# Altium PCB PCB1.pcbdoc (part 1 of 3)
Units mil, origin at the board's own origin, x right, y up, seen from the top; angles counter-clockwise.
Board outline 5971.11 x 4241.46 mil, 4 copper layers (Top Layer, Inner1, Inner2, Bottom Layer); 197 components, 112 nets, 603 pads, 396 vias.
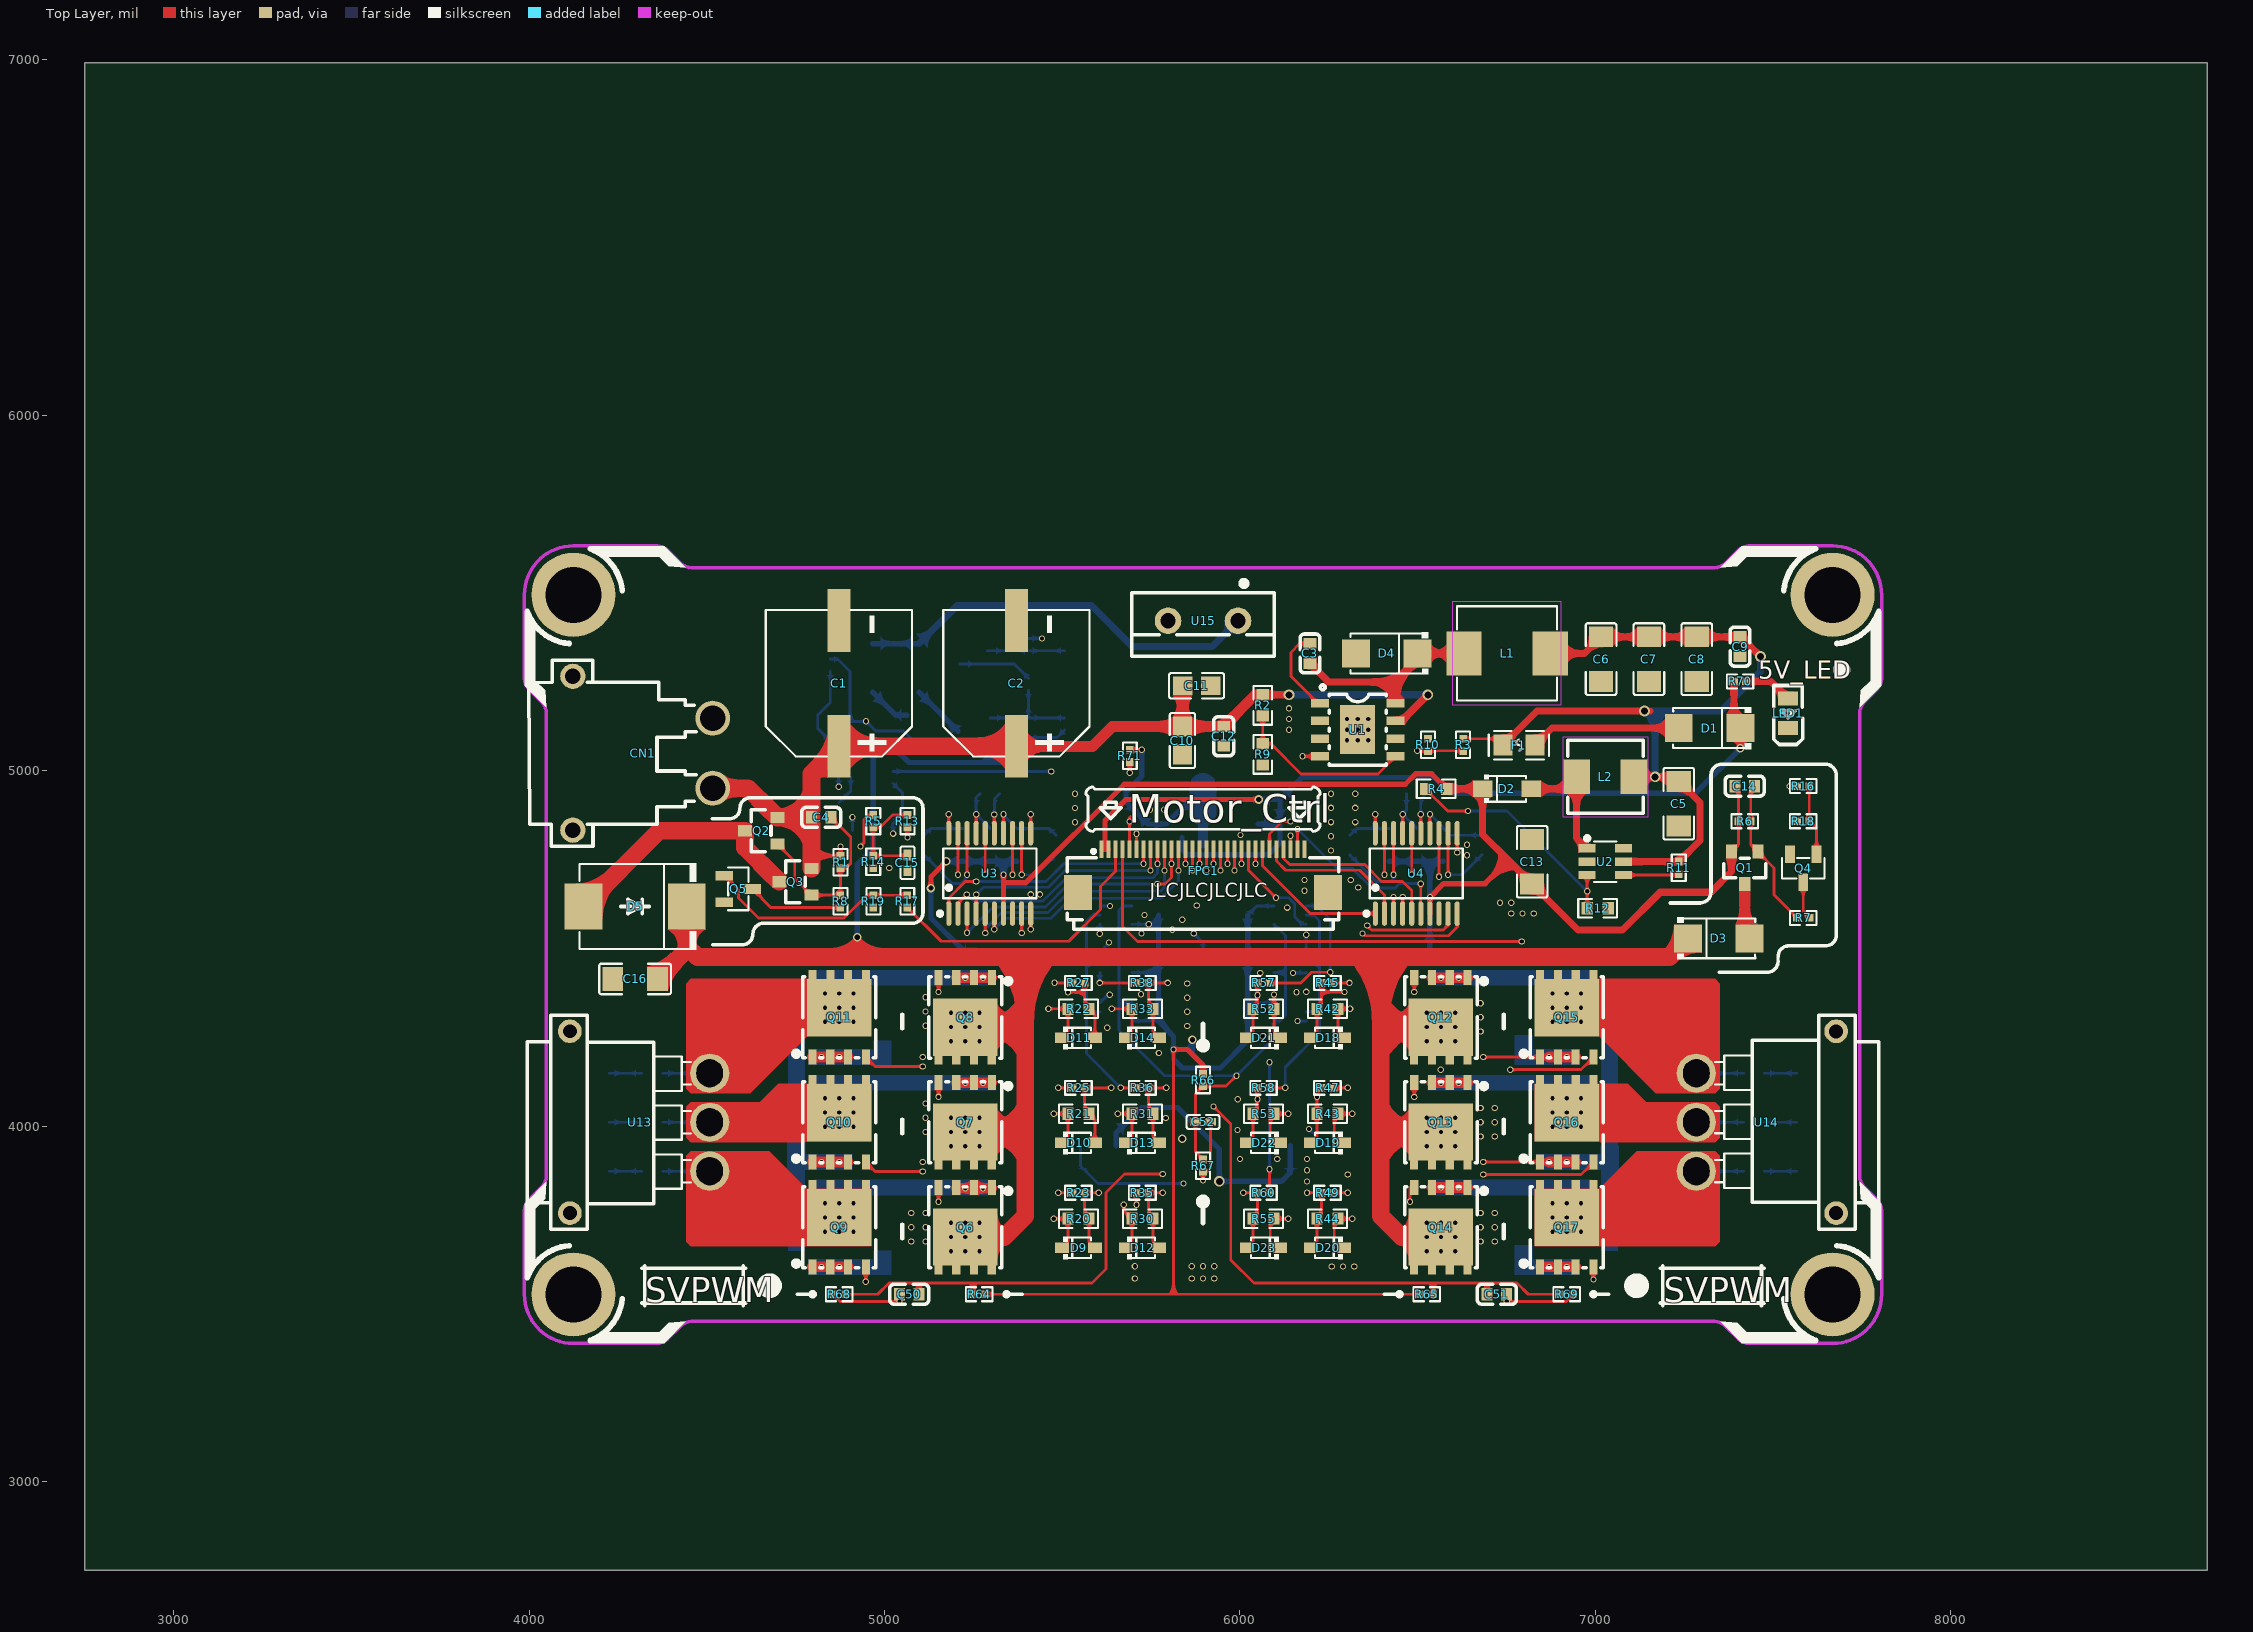
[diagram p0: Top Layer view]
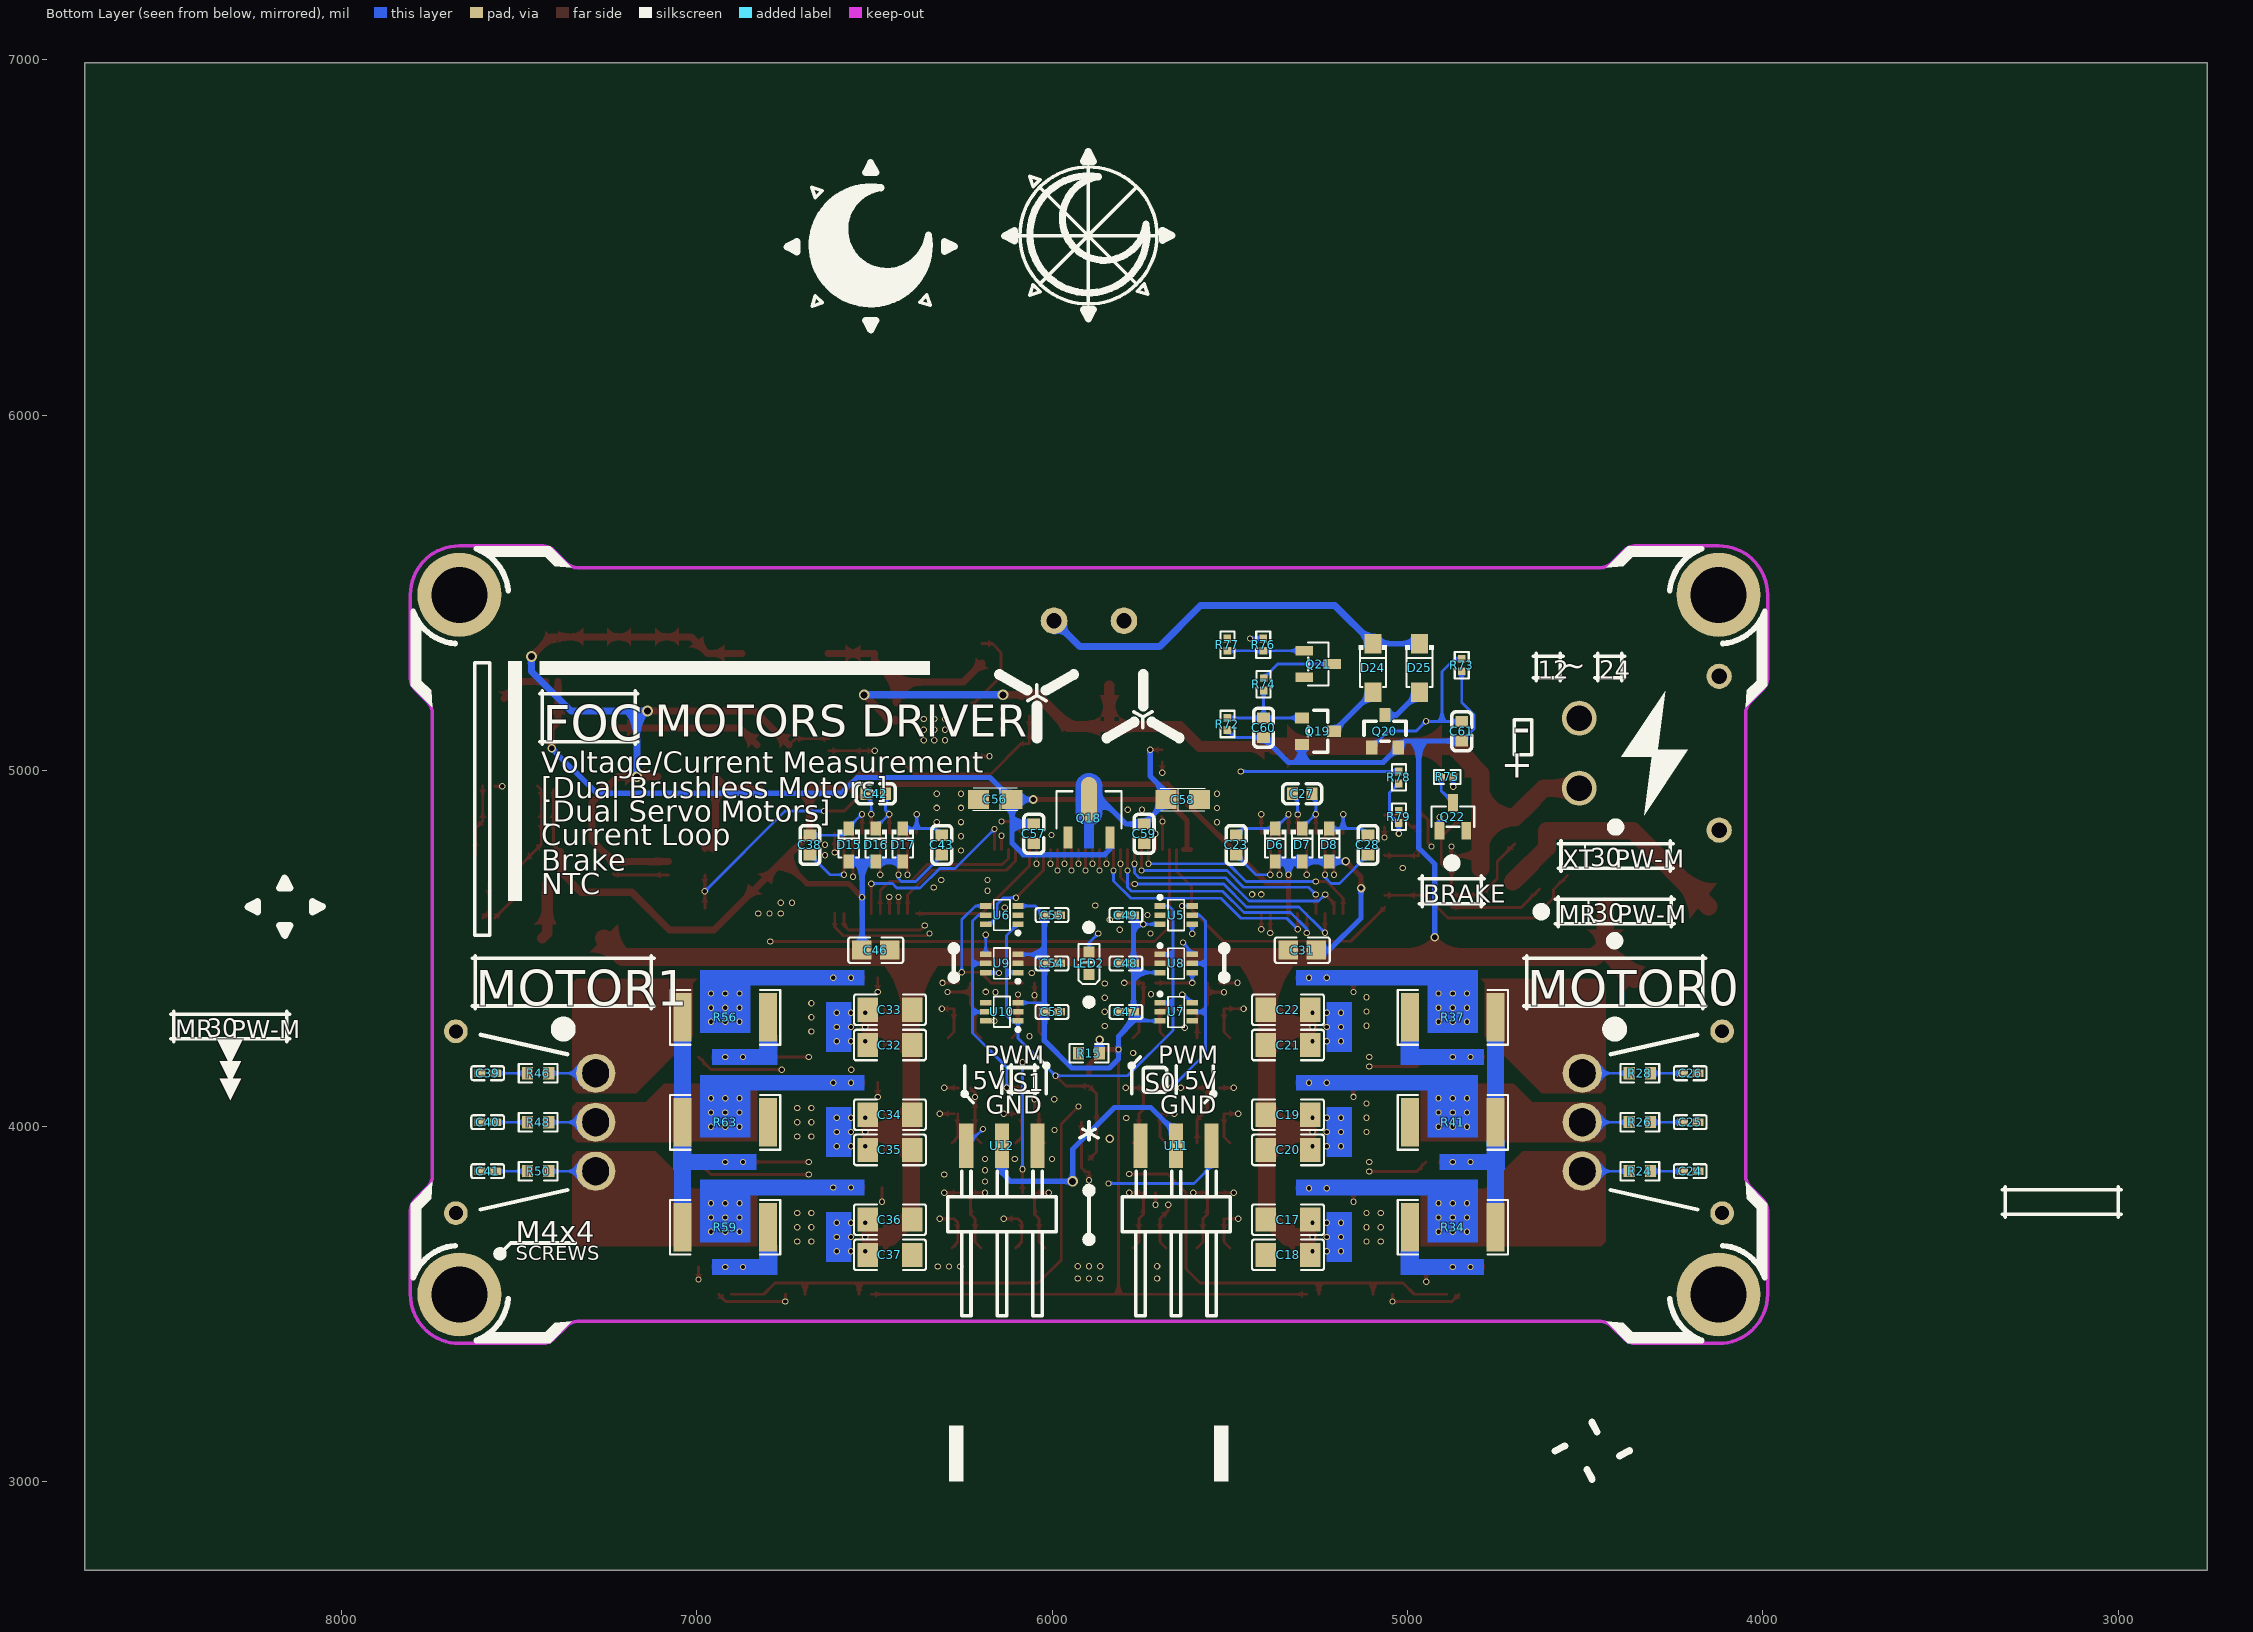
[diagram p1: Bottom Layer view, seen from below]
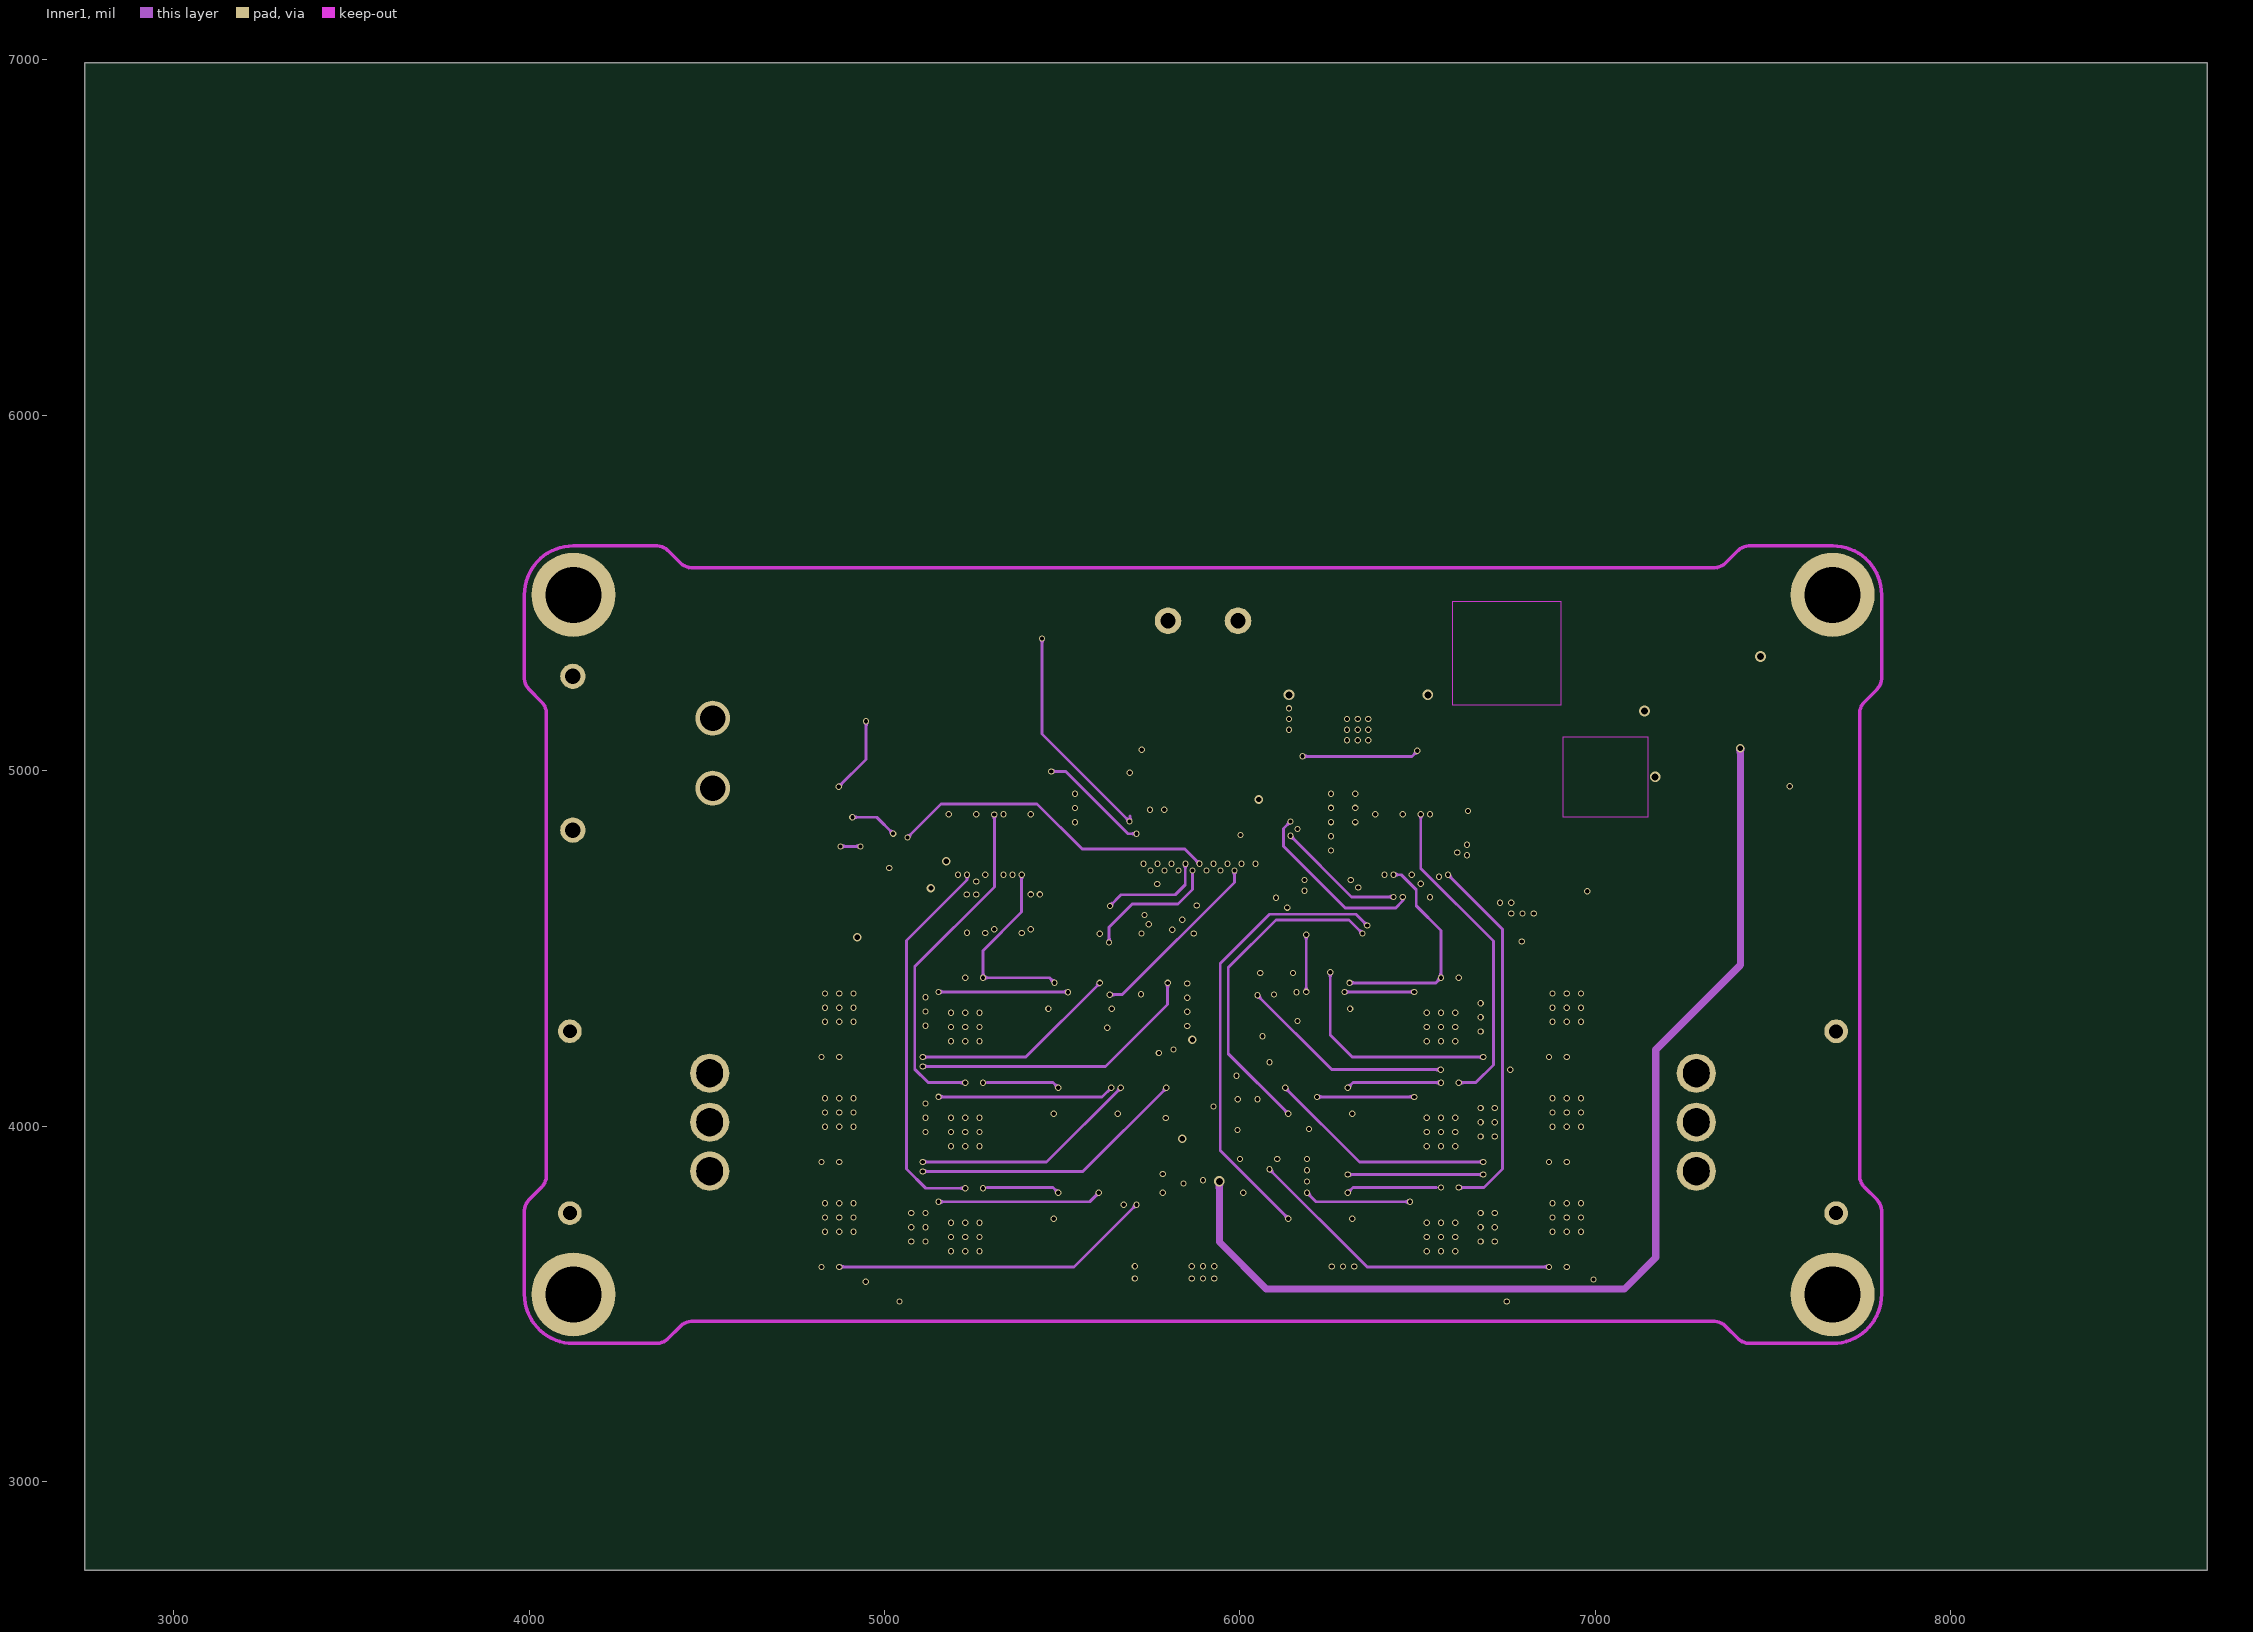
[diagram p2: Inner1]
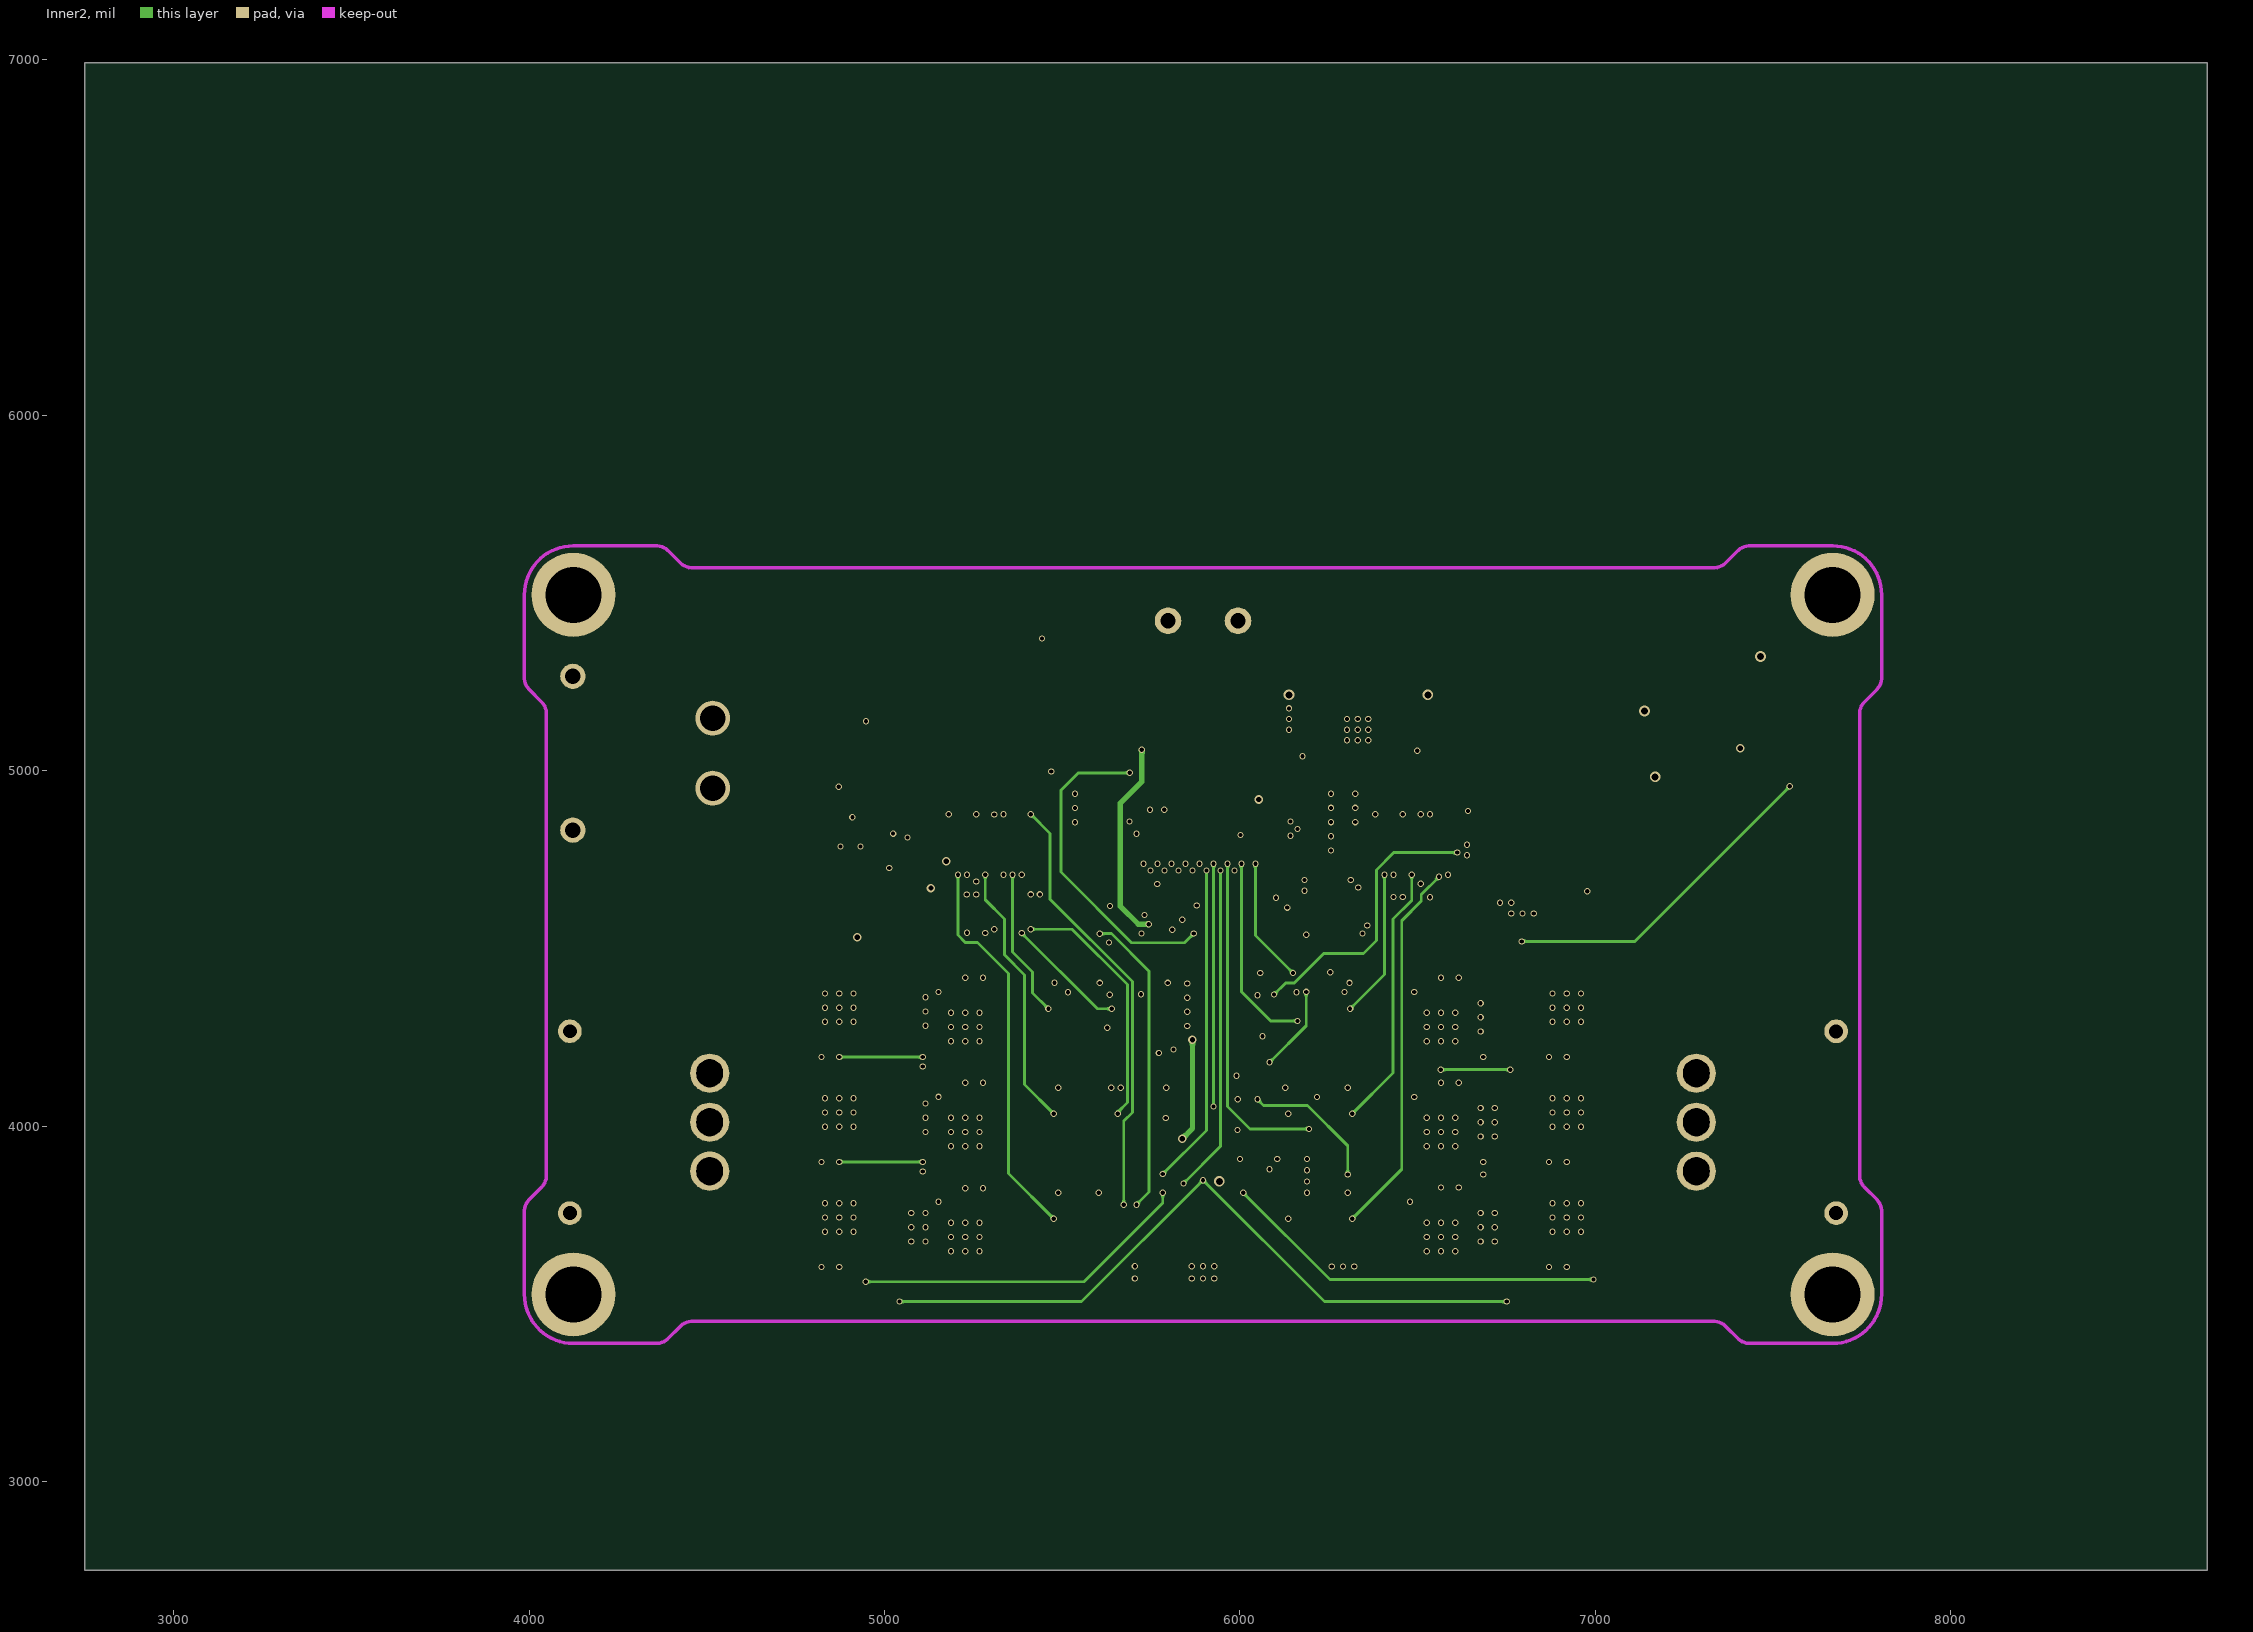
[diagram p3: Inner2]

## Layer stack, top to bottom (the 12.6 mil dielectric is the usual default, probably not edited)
Top Layer: signal copper (thickness not stored)
Dielectric: dielectric 12.6, FR-4, Dk 4.8
Inner1: signal copper (thickness not stored)
Dielectric: dielectric 12.6, FR-4, Dk 4.8
Inner2: signal copper (thickness not stored)
Dielectric: dielectric 12.6, FR-4, Dk 4.8
Bottom Layer: signal copper (thickness not stored)

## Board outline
8721.11,2750 2750,2750 2750,6991.46 8721.11,6991.46

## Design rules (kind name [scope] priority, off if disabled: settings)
BoardOutlineClearance copperThickness1oz [All] p0: genericclearance=10 ignorepadtopadclearanceinfootprint=FALSE except(0: Arc-SplitContinuation Track-SplitContinuation SMDPad-SplitContinuation THPad-SplitContinuation Via-SplitContinuation Fill-SplitContinuation Poly-SplitContinuation Region-SplitContinuation Text-SplitContinuation; 6: Track-CutoutEdge SMDPad-CutoutEdge THPad-CutoutEdge Via-CutoutEdge Region-CutoutEdge; 11.8: Track-OutlineEdge SMDPad-OutlineEdge THPad-OutlineEdge Via-OutlineEdge Fill-OutlineEdge Region-OutlineEdge Poly-OutlineEdge Text-OutlineEdge Fill-CutoutEdge)
BoardOutlineClearance copperThickness2oz [All] p0: genericclearance=10 ignorepadtopadclearanceinfootprint=FALSE except(0: Arc-SplitContinuation Track-SplitContinuation SMDPad-SplitContinuation THPad-SplitContinuation Via-SplitContinuation Fill-SplitContinuation Poly-SplitContinuation Region-SplitContinuation Text-SplitContinuation; 6: Track-CutoutEdge SMDPad-CutoutEdge THPad-CutoutEdge Via-CutoutEdge Region-CutoutEdge; 11.8: Track-OutlineEdge SMDPad-OutlineEdge THPad-OutlineEdge Via-OutlineEdge Fill-OutlineEdge Region-OutlineEdge Poly-OutlineEdge Text-OutlineEdge Fill-CutoutEdge)
Clearance copperThickness1oz [(InNet('POWER_ADC') OR InNet('M1_TIM1_CH3N') OR InNet('M1_TIM1_CH3') OR InNet('M1_TIM1_CH2N') OR InNet('M1_TIM1_CH2') OR InNet('M1_TIM1_CH1N') OR InNet('M1_TIM1_CH1') OR InNet('M0_U') OR InNet('M0_V') OR InNet('M1_U') OR InNet('M1_V') OR InNet('M1_W') OR InNet('VIN') OR InNet('M0_ISENSOR_NA') OR InNet('M0_W') OR InNet('M1_ISENSOR_NA') OR InNet('$1N124629') OR InNet('M0_ISENSOR_PA') OR InNet('M0_ISENSOR_PC') OR InNet('M1_ISENSOR_PA') OR InNet('M1_ISENSOR_PC') OR InNet('$1N64887') OR InNet('$1N69829') OR InNet('+5.8V') OR InNet('MOTOR_EN1') OR InNet('$1N64889') OR InNet('$1N20219') OR InNet('$1N20215') OR InNet('$1N1850') OR InNet('+5V') OR InNet('$1N36343') OR InNet('+12V') OR InNet('$1N79068') OR InNet('M1_HC') OR InNet('M1_LC') OR InNet('$1N213205') OR InNet('$1N2022') OR InNet('$1N915') OR InNet('$1N20187') OR InNet('+3.3V') OR InNet('DGND') OR InNet('M1_ADC_A') OR InNet('$1N20194') OR InNet('M1_TIM8_CH2N') OR InNet('M1_TIM8_CH1') OR InNet('M1_TIM8_CH3N') OR InNet('M1_TIM8_CH1N') OR InNet('$1N168458') OR InNet('M1_HA') OR InNet('M1_TIM8_CH2') OR InNet('PVCC') OR InNet('$1N20256') OR InNet('$1N167795') OR InNet('$1N168264') OR InNet('M1_HB') OR InNet('$1N20257') OR InNet('PGND') OR InNet('M1_ADC_C') OR InNet('M1_LB') OR InNet('M1_LA') OR InNet('$1N20159') OR InNet('$1N20164') OR InNet('$1N20229') OR InNet('M1_TIM8_CH3') OR InNet('$1N168255') OR InNet('M0_LC') OR InNet('$1N11350') OR InNet('M0_TIM1_CH1N') OR InNet('M0_ADC_A') OR InNet('M0_ADC_C') OR InNet('VOLTAGE_ADC') OR InNet('S0_PWM') OR InNet('S1_PWM') OR InNet('M0_ADC') OR InNet('M1_ADC') OR InNet('$1N10733') OR InNet('M0_LB') OR InNet('M0_BK_OUT') OR InNet('$1N36459') OR InNet('M1_BK_OUT') OR InNet('M0_TIM1_CH3') OR InNet('M0_TIM1_CH3N') OR InNet('M0_HC') OR InNet('M0_TIM1_CH2') OR InNet('M0_TIM1_CH2N') OR InNet('M0_TIM1_CH1') OR InNet('MOTOR_EN2') OR InNet('$1N11388') OR InNet('$1N10771') OR InNet('$1N7802') OR InNet('M0_HB') OR InNet('M0_LA') OR InNet('$1N8638') OR InNet('$1N9358') OR InNet('$1N7751') OR InNet('M0_HA') OR InNet('$1N7797') OR InNet('$1N3202') OR InNet('$1N3206') OR InNet('$1N3210') OR InNet('$1N3644') OR InNet('$1N10760') OR InNet('$1N9075') OR InNet('$1N11377') OR InNet('$1N126467') OR InNet('$1N126474') OR InNet('$1N126462') OR InNet('$1N126455') OR InNet('$1N126564') OR InNet('$1N126042') OR InNet('$1N126057') OR InNet('$1N126056') OR InNet('$1N126058') OR InNet('$1N20191') OR InNet('$1N20218') OR InNet('$1N20183') OR InNet('VREF') OR InNet('TEMP1_ADC') OR InNet('TEMP0_ADC'))] p1: gap=7 ignorepadtopadclearanceinfootprint=FALSE except(4: Track-Track; 6: Track-SMDPad SMDPad-SMDPad Track-THPad SMDPad-THPad THPad-THPad Track-Via SMDPad-Via THPad-Via Via-Via SMDPad-Fill THPad-Fill Via-Fill Fill-Fill Track-Region SMDPad-Region THPad-Region Via-Region Region-Region Track-Poly SMDPad-Poly THPad-Poly Via-Poly Fill-Poly Region-Poly Poly-Poly Track-Text SMDPad-Text THPad-Text Via-Text Fill-Text Region-Text Poly-Text Text-Text; 6.9: Track-Hole SMDPad-Hole THPad-Hole Via-Hole Fill-Hole Region-Hole Poly-Hole Text-Hole Sheet-Hole; 11.8: Track-Fill Fill-Region Track-Sheet SMDPad-Sheet THPad-Sheet Via-Sheet Fill-Sheet Region-Sheet Poly-Sheet Text-Sheet)
Clearance copperThickness2oz [All] p1: gap=7 ignorepadtopadclearanceinfootprint=FALSE except(6: Track-SMDPad SMDPad-SMDPad Track-THPad SMDPad-THPad THPad-THPad Track-Via SMDPad-Via THPad-Via Via-Via SMDPad-Fill THPad-Fill Via-Fill Fill-Fill Track-Region SMDPad-Region THPad-Region Via-Region Region-Region Track-Poly SMDPad-Poly THPad-Poly Via-Poly Fill-Poly Region-Poly Poly-Poly Track-Text SMDPad-Text THPad-Text Via-Text Fill-Text Region-Text Poly-Text Text-Text; 6.9: Track-Hole SMDPad-Hole THPad-Hole Via-Hole Fill-Hole Region-Hole Poly-Hole Text-Hole Sheet-Hole; 8: Track-Track; 11.8: Track-Fill Fill-Region Track-Sheet SMDPad-Sheet THPad-Sheet Via-Sheet Fill-Sheet Region-Sheet Poly-Sheet Text-Sheet)
DiffPairsRouting differentialPair [All] p1: maxuncoupledlength=10 minlimit=6 maxlimit=6 mostfreqgap=6 toplayer_minwidth=5 toplayer_prefwidth=10 toplayer_maxwidth=100 bottomlayer_minwidth=5 bottomlayer_prefwidth=10 bottomlayer_maxwidth=100 midlayer1_minwidth=5 midlayer1_prefwidth=10 midlayer1_maxwidth=100 midlayer2_minwidth=5 midlayer2_prefwidth=10 midlayer2_maxwidth=100
PasteMaskExpansion pasteMaskExpansion [All] p1: expansion=0
PlaneConnect innerPlane [All] p1: planeconnectstyle=Relief reliefexpansion=20 reliefentries=4 reliefconductorwidth=10 reliefairgap=10
PolygonConnect copperRegion [All] p1: connectstyle=Direct reliefentries=4 reliefconductorwidth=10 polygonreliefangle="90 Angle" airgapwidth=10
RoutingVias viaSize [All] p1: viastyle="Through Hole" holewidth=12 minholewidth=11.8 maxholewidth=248 width=24 minwidth=17.7 maxwidth=393.7
SolderMaskExpansion solderMaskExpansion [All] p1: useseparateexpansions=TRUE expansion=2 expansionbottom=2
Width copperThickness1oz [All] p1: maxlimit=100 minlimit=5 preferedwidth=10
Width copperThickness2oz [All] p1: maxlimit=100 minlimit=8 preferedwidth=10

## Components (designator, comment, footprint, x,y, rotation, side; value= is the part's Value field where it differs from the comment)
C1 "VMME0841J101MV" CAP-SMD_BD10.0-L10.3-W10.3-FD 4871.37,5245.96 r90 top
C2 "VMME0841J101MV" CAP-SMD_BD10.0-L10.3-W10.3-FD 5371.01,5245.96 r90 top
C3 "CC0603JRX7R9BB103" C0603 6197.01,5329.96 r270 top
C4 "CC0603KRX7R9BB104" C0603 4821.71,4868.66 r180 top
C5 "HGC1206R5476M100NSPJ" C1206 7234.57,4906.96 r90 top
C6 "HGC1206R5476M100NSPJ" C1206 7016.01,5313.96 r90 top
C7 "HGC1206R5476M100NSPJ" C1206 7150.69,5313.96 r90 top
C8 "HGC1206R5476M100NSPJ" C1206 7285.38,5313.96 r90 top
C9 "CC0603KRX7R9BB104" C0603 7407.01,5349.1 r270 top
C10 "CL21A475KBQNNNE" C0805 5838.01,5084.96 r90 top
C11 "CL21A475KBQNNNE" C0805 5878.01,5238.96 r180 top
C12 "CC0603KRX7R9BB104" C0603 5954.01,5096.83 r90 top
C13 "HGC1206R5476M250NSPJ" C1206 6821.98,4743.96 r270 top
C14 "CC0603KRX7R9BB104" C0603 7420.23,4956.63 r180 top
C15 "0402B222K500NT" C0402 5064.42,4740.98 r90 top
C16 "HGC1206R5476M100NSPJ" C1206 4298.02,4413.96 r0 top
C17 "CGA1206X5R226M350NT" C1206 5335.98,3736.85 r180 bottom
C18 "CGA1206X5R226M350NT" C1206 5335.98,3637.65 r180 bottom
C19 "CGA1206X5R226M350NT" C1206 5335.98,4032.16 r180 bottom
C20 "CGA1206X5R226M350NT" C1206 5335.98,3932.85 r180 bottom
C21 "CGA1206X5R226M350NT" C1206 5335.98,4228.16 r180 bottom
C22 "CGA1206X5R226M350NT" C1206 5335.98,4327.48 r180 bottom
C23 "CC0603KRX7R9BB104" C0603 5482.01,4790.96 r270 bottom
C24 "CC0402KRX7R9BB102" C0402 4203.98,3873.16 r180 bottom
C25 "CC0402KRX7R9BB102" C0402 4203.98,4010.96 r180 bottom
C26 "CC0402KRX7R9BB102" C0402 4203.98,4148.76 r180 bottom
C27 "CC0603KRX7R9BB104" C0603 5295.98,4934.96 r0 bottom
C28 "CC0603KRX7R9BB104" C0603 5110.98,4790.96 r270 bottom
C31 "HGC0805R5106K500NSLJ" C0805 5295.98,4494.96 r180 bottom
C32 "CGA1206X5R226M350NT" C1206 6455.98,4228.18 r0 bottom
C33 "CGA1206X5R226M350NT" C1206 6455.98,4327.48 r0 bottom
C34 "CGA1206X5R226M350NT" C1206 6455.98,4032.16 r0 bottom
C35 "CGA1206X5R226M350NT" C1206 6455.98,3932.86 r0 bottom
C36 "CGA1206X5R226M350NT" C1206 6455.98,3736.85 r0 bottom
C37 "CGA1206X5R226M350NT" C1206 6455.98,3637.65 r0 bottom
C38 "CC0603KRX7R9BB104" C0603 6680.98,4790.96 r270 bottom
C39 "CC0402KRX7R9BB102" C0402 7587.98,4148.76 r0 bottom
C40 "CC0402KRX7R9BB102" C0402 7587.98,4010.96 r0 bottom
C41 "CC0402KRX7R9BB102" C0402 7587.98,3873.16 r0 bottom
C42 "CC0603KRX7R9BB104" C0603 6495.98,4934.96 r0 bottom
C43 "CC0603KRX7R9BB104" C0603 6310.01,4790.96 r270 bottom
C46 "HGC0805R5106K500NSLJ" C0805 6495.98,4494.96 r0 bottom
C47 "CL05B104KO5NNNC" C0402 5791.98,4321.46 r180 bottom
C48 "CL05B104KO5NNNC" C0402 5791.98,4457.66 r180 bottom
C49 "CL05B104KO5NNNC" C0402 5791.98,4593.76 r180 bottom
C50 "CC0603KRX7R9BB104" C0603 5069.23,3526.86 r0 top
C51 "CC0603KRX7R9BB104" C0603 6722.73,3526.86 r180 top
C52 "CL05B104KO5NNNC" C0402 5895.98,4011.66 r180 top
C53 "CL05B104KO5NNNC" C0402 5999.98,4321.46 r0 bottom
C54 "CL05B104KO5NNNC" C0402 5999.98,4457.66 r0 bottom
C55 "CL05B104KO5NNNC" C0402 5999.98,4593.76 r0 bottom
C56 "TAJA226K010RNJ" CASE-A_3216 6159.98,4918.96 r0 bottom
C57 "CC0603KRX7R9BB104" C0603 6050.98,4822.46 r90 bottom
C58 "TAJA226K010RNJ" CASE-A_3216 5631.98,4918.96 r180 bottom
C59 "CC0603KRX7R9BB104" C0603 5740.98,4822.46 r90 bottom
C60 "CC0603KRX7R9BB104" C0603 5404.85,5120.8 r270 bottom
C61 "CC0603KRX7R9BB104" C0603 4847.11,5110.96 r270 bottom
CN1 "XT30PW-M" CONN-TH_XT30PW-M 4319.63,5049.18 r270 top locked
D1 "SS34_C8678" SMA_L4.3-W2.6-LS5.2-RD 7321.18,5119.96 r180 top
D2 "DSK34_C7502709" SOD-123FL_L2.7-W1.8-LS3.8-RD 6751.01,4948.96 r0 top
D3 "SS34_C8678" SMA_L4.3-W2.6-LS5.2-RD 7347.47,4528.42 r0 top
D4 "SS34_C8678" SMA_L4.3-W2.6-LS5.2-RD 6413.01,5329.96 r180 top
D5 "SK104C_C18199211" SMC_L6.9-W5.9-LS7.9-RD 4298.02,4617.96 r180 top
D6 "1N5819WS_C191023" SOD-323_L1.8-W1.3-LS2.5-RD 5372.01,4790.96 r270 bottom
D7 "1N5819WS_C191023" SOD-323_L1.8-W1.3-LS2.5-RD 5295.98,4790.96 r270 bottom
D8 "1N5819WS_C191023" SOD-323_L1.8-W1.3-LS2.5-RD 5220.01,4790.96 r270 bottom
D9 "1N5819WS_C191023" SOD-323_L1.8-W1.3-LS2.5-RD 5545.67,3657.46 r0 top
D10 "1N5819WS_C191023" SOD-323_L1.8-W1.3-LS2.5-RD 5545.67,3952.66 r0 top
D11 "1N5819WS_C191023" SOD-323_L1.8-W1.3-LS2.5-RD 5545.67,4247.96 r0 top
D12 "1N5819WS_C191023" SOD-323_L1.8-W1.3-LS2.5-RD 5725.67,3657.46 r0 top
D13 "1N5819WS_C191023" SOD-323_L1.8-W1.3-LS2.5-RD 5725.67,3952.66 r0 top
D14 "1N5819WS_C191023" SOD-323_L1.8-W1.3-LS2.5-RD 5725.67,4247.96 r0 top
D15 "1N5819WS_C191023" SOD-323_L1.8-W1.3-LS2.5-RD 6571.98,4790.96 r270 bottom
D16 "1N5819WS_C191023" SOD-323_L1.8-W1.3-LS2.5-RD 6495.98,4790.96 r270 bottom
D17 "1N5819WS_C191023" SOD-323_L1.8-W1.3-LS2.5-RD 6419.98,4790.96 r270 bottom
D18 "1N5819WS_C191023" SOD-323_L1.8-W1.3-LS2.5-RD 6246.28,4247.96 r180 top
D19 "1N5819WS_C191023" SOD-323_L1.8-W1.3-LS2.5-RD 6246.28,3952.66 r180 top
D20 "1N5819WS_C191023" SOD-323_L1.8-W1.3-LS2.5-RD 6246.28,3657.46 r180 top
D21 "1N5819WS_C191023" SOD-323_L1.8-W1.3-LS2.5-RD 6066.28,4247.96 r180 top
D22 "1N5819WS_C191023" SOD-323_L1.8-W1.3-LS2.5-RD 6066.28,3952.66 r180 top
D23 "1N5819WS_C191023" SOD-323_L1.8-W1.3-LS2.5-RD 6066.28,3657.46 r180 top
D24 "DSK34_C7502709" SOD-123FL_L2.7-W1.8-LS3.8-RD 5097.01,5289.27 r270 bottom
D25 "DSK34_C7502709" SOD-123FL_L2.7-W1.8-LS3.8-RD 4966.01,5289.27 r270 bottom
F1 "SMD0805-100" F0805 6784.98,5071.96 r0 top
FPC1 "FPC-05F-30PH20" FPC-SMD_30P-P0.50_XUNPU_FPC-05F-30PH20 5895.98,4717.86 r0 top locked
L1 "SMMS0630-220M" IND-SMD_L7.3-W6.6_MHCI06030 6751.51,5329.96 r0 top
L2 "FXL0530-100-M" IND-SMD_L5.4-W5.2_FXL0530 7028.01,4982.96 r180 top
LED1 "KT-0805Y" LED0805-R-RD 7542.01,5161.31 r90 top locked
LED2 "NCD0603G1" LED0603-RD_1 5896.01,4457.96 r90 bottom
Q1 "WST4041" SOT-23_L2.9-W1.3-P1.90-LS2.4-BR 7420.23,4726.72 r90 top
Q2 "WST4041" SOT-23_L2.9-W1.3-P1.90-LS2.4-BR 4652.86,4831.26 r0 top
Q3 "WST4041" SOT-23_L2.9-W1.3-P1.90-LS2.4-BR 4748.91,4687.26 r0 top
Q4 "S8050" SOT-23-3_L2.9-W1.3-P1.90-LS2.4-BR 7584.87,4725.73 r90 top
Q5 "S8050" SOT-23-3_L2.9-W1.3-P1.90-LS2.4-BR 4588.58,4667.26 r180 top
Q6 "KNY3406C" PDFN-8_L4.9-W5.8-P1.27-LS6.1-BL 5226.69,3715.46 r180 top
Q7 "KNY3406C" PDFN-8_L4.9-W5.8-P1.27-LS6.1-BL 5226.69,4010.66 r180 top
Q8 "KNY3406C" PDFN-8_L4.9-W5.8-P1.27-LS6.1-BL 5226.69,4305.96 r180 top
Q9 "KNY3406C" PDFN-8_L4.9-W5.8-P1.27-LS6.1-BL 4872.36,3715.46 r0 top locked
Q10 "KNY3406C" PDFN-8_L4.9-W5.8-P1.27-LS6.1-BL 4872.36,4010.71 r0 top locked
Q11 "KNY3406C" PDFN-8_L4.9-W5.8-P1.27-LS6.1-BL 4872.36,4305.96 r0 top locked
Q12 "KNY3406C" PDFN-8_L4.9-W5.8-P1.27-LS6.1-BL 6565.27,4305.96 r180 top
Q13 "KNY3406C" PDFN-8_L4.9-W5.8-P1.27-LS6.1-BL 6565.27,4010.66 r180 top
Q14 "KNY3406C" PDFN-8_L4.9-W5.8-P1.27-LS6.1-BL 6565.27,3715.46 r180 top
Q15 "KNY3406C" PDFN-8_L4.9-W5.8-P1.27-LS6.1-BL 6919.6,4305.99 r0 top
Q16 "KNY3406C" PDFN-8_L4.9-W5.8-P1.27-LS6.1-BL 6919.6,4010.71 r0 top
Q17 "KNY3406C" PDFN-8_L4.9-W5.8-P1.27-LS6.1-BL 6919.6,3715.44 r0 top
Q18 "AMS1117-3.3V_C5120796" SOT-89-3_L4.5-W2.5-P1.50-LS4.2-BR 5896.01,4865.57 r270 bottom
Q19 "WST4041" SOT-23_L2.9-W1.3-P1.90-LS2.4-BR 5252.01,5110.96 r0 bottom
Q20 "WST4041" SOT-23_L2.9-W1.3-P1.90-LS2.4-BR 5063.09,5110.96 r270 bottom
Q21 "S8050" SOT-23-3_L2.9-W1.3-P1.90-LS2.4-BR 5250.57,5300.19 r0 bottom
Q22 "S8050" SOT-23-3_L2.9-W1.3-P1.90-LS2.4-BR 4872.01,4870.96 r270 bottom
R1 "0402WGF1002TCE" R0402 4876.01,4742.72 r90 top
R2 "0603WAF3303T5E" R0603 6064.01,5183.9 r90 top
R3 "0402WGF1152TCE" R0402 6627.82,5072.96 r90 top
R4 "0603WAF6802T5E" R0603 6551.98,4948.96 r0 top
R5 "0402WGF1003TCE" R0402 4968.11,4858.36 r90 top
R6 "0402WGF1002TCE" R0402 7420.23,4857.68 r180 top
R7 "0402WGF1002TCE" R0402 7584.88,4585.95 r180 top
R8 "0402WGF1002TCE" R0402 4875.61,4632.49 r90 top
R9 "0603WAF6802T5E" R0603 6064.01,5045.96 r90 top
R10 "0402WGF3301TCE" R0402 6529.01,5072.96 r270 top
R11 "0402WGF1002TCE" R0402 7234.57,4726.94 r90 top
R12 "FRC0603F3401TS" R0603 7006.47,4612.96 r180 top
R13 "FRC0402J102 TS" R0402 5064.42,4858.33 r90 top
R14 "0402WGF1002TCE" R0402 4968.11,4743.54 r270 top
R15 "0603WAF0000T5E" R0603 5895.98,4204.96 r180 bottom
R16 "0402WGF1002TCE" R0402 7584.87,4956.64 r180 top
R17 "0402WGF1002TCE" R0402 5063.96,4632.49 r270 top
R18 "0402WGF1002TCE" R0402 7584.87,4857.68 r180 top
R19 "0402WGF1002TCE" R0402 4968.72,4632.49 r270 top
R20 "0603WAF100JT5E" R0603 5545.67,3739.49 r0 top
R21 "0603WAF100JT5E" R0603 5545.67,4034.69 r0 top
R22 "0603WAF100JT5E" R0603 5545.67,4329.99 r0 top
R23 "0402WGF2002TCE" R0402 5545.67,3812.46 r0 top
R24 "0603WAF100JT5E" R0603 4345.98,3873.16 r0 bottom
R25 "0402WGF2002TCE" R0402 5545.67,4107.66 r0 top
R26 "0603WAF100JT5E" R0603 4345.98,4010.96 r0 bottom
R27 "0402WGF2002TCE" R0402 5545.67,4402.96 r0 top
R28 "0603WAF100JT5E" R0603 4345.98,4148.76 r0 bottom
R30 "0603WAF100JT5E" R0603 5725.67,3739.49 r0 top
R31 "0603WAF100JT5E" R0603 5725.67,4034.69 r0 top
R33 "0603WAF100JT5E" R0603 5725.67,4329.99 r0 top
R34 "PA2512FKE7T0R01E" R2512 4872.38,3715.46 r0 bottom
R35 "0402WGF2002TCE" R0402 5725.67,3812.46 r0 top
R36 "0402WGF2002TCE" R0402 5725.67,4107.66 r0 top
R37 "PA2512FKE7T0R01E" R2512 4872.38,4305.96 r0 bottom
R38 "0402WGF2002TCE" R0402 5725.67,4402.96 r0 top
R41 "PA2512FKE7T0R01E" R2512 4872.38,4010.66 r180 bottom
R42 "0603WAF100JT5E" R0603 6246.28,4329.99 r180 top
R43 "0603WAF100JT5E" R0603 6246.28,4034.69 r180 top
R44 "0603WAF100JT5E" R0603 6246.28,3739.49 r180 top
R45 "0402WGF2002TCE" R0402 6246.28,4402.96 r180 top
R46 "0603WAF100JT5E" R0603 7445.98,4148.76 r180 bottom
R47 "0402WGF2002TCE" R0402 6246.28,4107.66 r180 top
R48 "0603WAF100JT5E" R0603 7445.98,4010.95 r180 bottom
R49 "0402WGF2002TCE" R0402 6246.28,3812.46 r180 top
R50 "0603WAF100JT5E" R0603 7445.98,3873.16 r180 bottom
R52 "0603WAF100JT5E" R0603 6066.28,4329.99 r180 top
R53 "0603WAF100JT5E" R0603 6066.28,4034.69 r180 top
R55 "0603WAF100JT5E" R0603 6066.28,3739.49 r180 top
R56 "PA2512FKE7T0R01E" R2512 6919.58,4305.96 r180 bottom
R57 "0402WGF2002TCE" R0402 6066.28,4402.96 r180 top
R58 "0402WGF2002TCE" R0402 6066.28,4107.66 r180 top
R59 "PA2512FKE7T0R01E" R2512 6919.58,3715.46 r180 bottom
R60 "0402WGF2002TCE" R0402 6066.28,3812.46 r180 top
R63 "PA2512FKE7T0R01E" R2512 6919.58,4010.66 r0 bottom
R64 "NCP15XH103F03RC" R0402 5266.08,3526.84 r0 top
R65 "NCP15XH103F03RC" R0402 6525.88,3526.84 r180 top
R66 "0402WGF1002TCE" R0402 5895.98,4129.66 r270 top
R67 "0402WGF1002TCE" R0402 5895.98,3888.66 r270 top
R68 "FRC0402F3001TS" R0402 4872.38,3526.84 r0 top
R69 "FRC0402F3001TS" R0402 6919.58,3526.84 r180 top
R70 "0402WGF4701TCE" R0402 7407.01,5251.26 r180 top
R71 "FRC0402F3001TS" R0402 5690.01,5041.96 r90 top
R72 "0402WGF1002TCE" R0402 5506.57,5131.32 r270 bottom
R73 "0402WGF1002TCE" R0402 4847.11,5296.96 r270 bottom
R74 "0402WGF1002TCE" R0402 5404.85,5243.19 r270 bottom
R75 "0402WGF1002TCE" R0402 4887.83,4982.68 r180 bottom
R76 "0402WGF1002TCE" R0402 5405.57,5354.6 r90 bottom
R77 "0402WGF1002TCE" R0402 5506.57,5354.6 r90 bottom
R78 "0402WGF1002TCE" R0402 5024.01,4980.96 r90 bottom
R79 "0402WGF1002TCE" R0402 5024.01,4870.27 r90 bottom
U1 "TPS5430DDAR" ESOP-8_L4.9-W3.9-P1.27-LS6.0-TL-EP 6331.27,5115.34 r0 top
U2 "MT3608L" SOT-23-6_L2.9-W1.6-P0.95-LS2.8-BL_3 7027.99,4743.96 r270 top
U3 "FD6288T" TSSOP-20_L6.5-W4.4-P0.65-LS6.4-BL 5296.01,4710.96 r0 top locked
U4 "FD6288T" TSSOP-20_L6.5-W4.4-P0.65-LS6.4-BL 6496.01,4710.96 r0 top locked
U5 "TP181A1-CR" SC70-6_L2.1-W1.3-P0.65-LS2.3-BL 5650.98,4593.74 r270 bottom
U6 "TP181A1-CR" SC70-6_L2.1-W1.3-P0.65-LS2.3-BL 6140.98,4593.74 r90 bottom
U7 "TP181A1-CR" SC70-6_L2.1-W1.3-P0.65-LS2.3-BL 5650.98,4321.51 r270 bottom
U8 "TP181A1-CR" SC70-6_L2.1-W1.3-P0.65-LS2.3-BL 5650.98,4457.62 r270 bottom
U9 "TP181A1-CR" SC70-6_L2.1-W1.3-P0.65-LS2.3-BL 6140.98,4457.62 r90 bottom
U10 "TP181A1-CR" SC70-6_L2.1-W1.3-P0.65-LS2.3-BL 6140.98,4321.51 r90 bottom
U11 "KH-2.54PH-1X3P-L13.5-WT" HDR-SMD_3P-P2.54-H-M_KH-2.54PH-1X3P-L13.5-WT 5650.98,3944.96 r180 bottom locked
U12 "KH-2.54PH-1X3P-L13.5-WT" HDR-SMD_3P-P2.54-H-M_KH-2.54PH-1X3P-L13.5-WT 6140.98,3944.96 r180 bottom locked
U13 "MR30PW-M30.G.Y" CONN-TH_MR30PW-M30-G-Y 4311.08,4010.96 r270 top locked
U14 "MR30PW-M30.G.Y" CONN-TH_MR30PW-M30-G-Y 7480.85,4010.95 r90 top locked
U15 "TPAL0220F10R0K9" TO-220-2_L10.1-W4.5-P5.08-L 5896.01,5421.86 r180 top

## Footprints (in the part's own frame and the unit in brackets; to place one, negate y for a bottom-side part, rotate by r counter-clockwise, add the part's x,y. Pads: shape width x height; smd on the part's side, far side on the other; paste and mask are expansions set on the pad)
C0402 [mm]
  rect 0.79x0.54 smd: 1(-0.545,0) 2(0.545,0)
  silkscreen extent -1.17,-0.5 1.17,0.5
C0603 [mm]
  rect 0.8x0.9 smd: 1(-0.7,0) 2(0.7,0)
  silkscreen extent -1.39,-0.71 1.39,0.71
C0805 [mm]
  rect 1.41x1.35 smd: 1(-1,0) 2(1,0)
  silkscreen extent -1.96,-0.9 1.96,0.9
C1206 [mm]
  rect 1.485x1.728 smd: 1(-1.593,0) 2(1.593,0)
  silkscreen extent -2.56,-1.09 2.56,1.09
CAP-SMD_BD10.0-L10.3-W10.3-FD [mm]
  rect 4.5x1.65 smd: 1(-4.5,0) 2(4.5,0)
  silkscreen extent -5.23,-5.23 5.23,5.23
CASE-A_3216 [mil]
  rect 59.05x53.5 smd: 1(-47.24,0) 2(47.24,0)
  silkscreen extent -63,-32 63,32
CONN-TH_MR30PW-M30-G-Y [mm]
  round 2.8 hole 1.9 slot 1.995 at 0 deg: 1(-3.5,5) 2(0,5) 3(3.5,5)
  round 1.7 hole 1: 4(6.5,-5) 5(-6.5,-5)
  silkscreen extent -7.65,-8.05 7.65,3.65
CONN-TH_XT30PW-M [mm]
  round 2.5 hole 1.8: 1(-2.5,5) 2(2.5,5)
  round 1.8 hole 1.1: 3(5.5,-5) 4(-5.5,-5)
  silkscreen extent -6.65,-8.15 6.65,3.81
ESOP-8_L4.9-W3.9-P1.27-LS6.0-TL-EP [mm]
  rect 1.3x0.6 smd: 1(-2.7,1.905) 2(-2.7,0.635) 3(-2.7,-0.635) 4(-2.7,-1.905) 5(2.7,-1.905) 6(2.7,-0.635) 7(2.7,0.635) 8(2.7,1.905)
  rect 2.5x3.5 smd: 9(0,0)
  silkscreen extent -2.67,-2.55 2.05,3.2
F0805 [mm]
  rect 1.335x1.5 smd: 1(-1.142,0) 2(1.142,0)
  silkscreen extent -2.16,-1.02 2.16,1.02
FPC-SMD_30P-P0.50_XUNPU_FPC-05F-30PH20 [mm]
  rect 0.3x1.25 smd: 1(-7.25,1.538) 2(-6.75,1.538) 3(-6.25,1.538) 4(-5.75,1.538) 5(-5.25,1.538) 6(-4.75,1.538) 7(-4.25,1.538) 8(-3.75,1.538) 9(-3.25,1.538) 10(-2.75,1.538) 11(-2.25,1.538) 12(-1.75,1.538) 13(-1.25,1.538) 14(-0.75,1.538) 15(-0.25,1.538) 16(0.25,1.538) 17(0.75,1.538) 18(1.25,1.538) 19(1.75,1.538) 20(2.25,1.538) 21(2.75,1.538) 22(3.25,1.538) 23(3.75,1.538) 24(4.25,1.538) 25(4.75,1.538) 26(5.25,1.538) 27(5.75,1.538) 28(6.25,1.538) 29(6.75,1.538) 30(7.25,1.538)
  rect 2x2.5 smd: 31(8.94,-1.538) 32(-8.94,-1.538)
  silkscreen extent -9.7,-4.15 9.7,1.53
HDR-SMD_3P-P2.54-H-M_KH-2.54PH-1X3P-L13.5-WT [mm]
  rect 1.02x3.2 smd: 1(-2.54,0) 2(0,0) 3(2.54,0)
  silkscreen extent -3.86,-12.15 3.87,-1.83
IND-SMD_L5.4-W5.2_FXL0530 [mm]
  rect 1.9x2.5 smd: 1(-2.05,0) 2(2.05,0)
  silkscreen extent -2.7,-2.6 2.7,2.6
IND-SMD_L7.3-W6.6_MHCI06030 [mil]
  rect 99.4x122.8 smd: 1(-121.2,0) 2(121.2,0)
  silkscreen extent -141,-133 141,133
LED0603-RD_1 [mm]
  rect 0.8x0.8 smd: 1(-0.799,-0.004) 2(0.799,0.004)
  silkscreen extent -1.49,-0.75 1.39,0.76
LED0805-R-RD [mm]
  rect 1x1.4 smd: 1(1.05,0) 2(-1.05,0)
  silkscreen extent -2.22,-1.04 1.99,1.01
PDFN-8_L4.9-W5.8-P1.27-LS6.1-BL [mm]
  rect 0.58x1.079 smd: 1(-1.907,-2.835) 2(-0.637,-2.835) 3(0.633,-2.835) 4(1.903,-2.835)
  rect 0.58x1.08 smd: 5(1.907,2.835) 6(0.638,2.835) 7(-0.632,2.835) 8(-1.902,2.835)
  rect 4.6x4.1 smd: 9(-0.002,0.695)
  silkscreen extent -3.2,-2.89 2.6,2.9
R0402 [mm]
  rect 0.566x0.54 smd: 1(-0.433,0) 2(0.433,0)
  silkscreen extent -0.94,-0.5 0.94,0.5
R0603 [mil]
  rect 31.75x34.02 smd: 1(-29.66,0) 2(29.66,0)
  silkscreen extent -55,-26 55,26
R2512 [mil]
  rect 50.49x136.06 smd: 1(-120.72,0) 2(120.72,0)
  silkscreen extent -155,-77 155,77
SC70-6_L2.1-W1.3-P0.65-LS2.3-BL [mil]
  rect 15.7x31.5 smd: 1(-25.6,-45.3) 2(0,-45.3) 3(25.6,-45.3) 4(25.6,45.3) 5(0,45.3) 6(-25.6,45.3)
  silkscreen extent -55,-50 43,23
SMA_L4.3-W2.6-LS5.2-RD [mm]
  rect 2x2 smd: 1(-2.2,0) 2(2.2,0)
  silkscreen extent -2.98,-1.5 2.6,1.5
SMC_L6.9-W5.9-LS7.9-RD [mm]
  rect 2.7x3.3 smd: 1(-3.686,0) 2(3.686,0)
  silkscreen extent -4.36,-3.1 3.98,3.1
SOD-123FL_L2.7-W1.8-LS3.8-RD [mm]
  rect 1.4x1.2 smd: 1(-1.735,0) 2(1.735,0)
  silkscreen extent -1.6,-1 1.38,1
SOD-323_L1.8-W1.3-LS2.5-RD [mm]
  rect 1x0.75 smd: 1(-1.173,0) 2(1.173,0)
  silkscreen extent -1.08,-0.8 0.9,0.8
SOT-23-3_L2.9-W1.3-P1.90-LS2.4-BR [mm]
  rect 1.25x0.7 smd: 1(1,-0.95) 2(1,0.95) 3(-1,0)
  silkscreen extent -0.73,-1.53 0.73,1.53
SOT-23-6_L2.9-W1.6-P0.95-LS2.8-BL_3 [mm]
  rect 0.6x1.2 smd: 1(-0.95,-1.3) 2(0,-1.3) 3(0.95,-1.3) 4(0.95,1.3) 5(0,1.3) 6(-0.95,1.3)
  silkscreen extent -1.82,-1.45 1.45,0.8
SOT-23_L2.9-W1.3-P1.90-LS2.4-BR [mm]
  rect 1x0.8 smd: 1(1.15,-0.95) 2(1.15,0.95) 3(-1.15,0)
  silkscreen extent -0.7,-1.5 0.7,1.5
SOT-89-3_L4.5-W2.5-P1.50-LS4.2-BR [mm]
  rect 1.575x0.672 smd: 1(1.356,-1.5) 3(1.356,1.5)
  oval 3.226x1.14 smd: 2(-1.356,0)
  Top Layer region: -2.283,0.95 -0.429,0.95 -0.384,0.949 -0.34,0.946 -0.296,0.94 -0.252,0.933 -0.208,0.924 -0.165,0.912 -0.123,0.899 -0.081,0.884 -0.04,0.866 0,0.847 0.04,0.826 0.078,0.803 0.115,0.779 0.151,0.752 0.185,0.724 0.219,0.695 0.251,0.664 0.281,0.631 0.31,0.597 0.337,0.562 0.362,0.525 0.386,0.488 0.408,0.449 0.428,0.409 0.447,0.33 2.144,0.33 2.144,-0.33 0.447,-0.33 0.428,-0.409 0.408,-0.449 0.386,-0.488 0.362,-0.526 0.337,-0.562 0.31,-0.597 0.281,-0.631 0.251,-0.664 0.219,-0.695 0.185,-0.725 0.151,-0.753 0.115,-0.779 0.078,-0.804 0.04,-0.827 0,-0.848 -0.04,-0.867 -0.081,-0.884 -0.123,-0.899 -0.165,-0.913 -0.208,-0.924 -0.252,-0.934 -0.296,-0.941 -0.34,-0.946 -0.384,-0.949 -0.429,-0.95 -2.283,-0.95 -2.328,-0.949 -2.372,-0.946 -2.416,-0.941 -2.46,-0.934 -2.504,-0.924 -2.547,-0.913 -2.589,-0.899 -2.631,-0.884 -2.672,-0.867 -2.713,-0.848 -2.752,-0.827 -2.79,-0.804 -2.827,-0.779 -2.863,-0.753 -2.898,-0.725 -2.931,-0.695 -2.963,-0.664 -2.993,-0.631 -3.022,-0.597 -3.049,-0.562 -3.075,-0.526 -3.098,-0.488 -3.12,-0.449 -3.141,-0.409 -3.159,-0.369 -3.175,-0.327 -3.189,-0.285 -3.202,-0.242 -3.212,-0.199 -3.22,-0.155 -3.227,-0.111 -3.231,-0.067 -3.233,-0.022 -3.233,0.022 -3.231,0.067 -3.227,0.111 -3.22,0.155 -3.212,0.199 -3.202,0.242 -3.189,0.285 -3.175,0.327 -3.159,0.369 -3.141,0.409 -3.12,0.449 -3.098,0.488 -3.075,0.525 -3.049,0.562 -3.022,0.597 -2.993,0.631 -2.963,0.664 -2.931,0.695 -2.898,0.724 -2.863,0.752 -2.827,0.779 -2.79,0.803 -2.752,0.826 -2.713,0.847 -2.672,0.866 -2.631,0.884 -2.589,0.899 -2.547,0.912 -2.504,0.924 -2.46,0.933 -2.416,0.94 -2.372,0.946 -2.328,0.949
  silkscreen extent -1.95,-2.33 0.7,2.33
TO-220-2_L10.1-W4.5-P5.08-L [mm]
  round 1.9 hole 1.1: 1(-2.5,0) 2(2.5,0)
  silkscreen extent -5.08,-2.87 5.08,2.54
TSSOP-20_L6.5-W4.4-P0.65-LS6.4-BL [mil]
  oval 14.33x68.58 smd: 1(-115.16,-113.03) 2(-89.57,-113.03) 3(-63.98,-113.03) 4(-38.39,-113.03) 5(-12.79,-113.03) 6(12.8,-113.03) 7(38.39,-113.03) 8(63.98,-113.03) 9(89.57,-113.03) 10(115.16,-113.03) 11(115.16,113.03) 12(89.57,113.03) 13(63.98,113.03) 14(38.39,113.03) 15(12.8,113.03) 16(-12.79,113.03) 17(-38.39,113.03) 18(-63.98,113.03) 19(-89.57,113.03) 20(-115.16,113.03)
  silkscreen extent -146,-119 131,70

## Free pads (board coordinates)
  round 236.22 hole 157.48: 1(4124.33,3526.46) 1(4124.33,5494.96) 1(7667.64,3526.46) 1(7667.64,5494.96)

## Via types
v1: diameter 17.7, hole 12, Top Layer to Bottom Layer, 383 vias
v2: diameter 24, hole 15, Top Layer to Bottom Layer, 7 vias
v3: diameter 30, hole 19.7, Top Layer to Bottom Layer, 6 vias

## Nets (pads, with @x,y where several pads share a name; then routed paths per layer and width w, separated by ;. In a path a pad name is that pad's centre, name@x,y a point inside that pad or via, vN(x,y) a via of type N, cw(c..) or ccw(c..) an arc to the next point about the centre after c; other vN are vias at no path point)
$1N915: F1.2 | length 424.5
  Top Layer w20: F1.2@6829.96,5071.96 6877.96,5119.96 7234.57,5119.96
$1N1850: R11.1 U2.4 | length 156.8
  Top Layer w8: U2.4@7079.17,4706.56 7231.23,4706.56 R11.1@7234.57,4709.9
$1N2022: R4.1 R12.2 U2.3 | length 667.5
  Top Layer w8: R4.1@6522.32,4948.96 6584.82,4886.46 v1(6641.58,4886.46) ; R12.2@6976.81,4612.96 v1(6976.81,4660.64) U2.3@6976.81,4706.56
  Bottom Layer w8: v1(6641.58,4886.46) 6750.99,4886.46 v1(6976.81,4660.64)
$1N3202: Q5.1 R17.1 R19.1 | length 604.5
  Top Layer w8: Q5.1@4549.21,4704.66 4588.58,4665.29 4588.58,4642.16 4645.68,4585.06 4885.98,4585.06 4950.45,4649.53 R19.1@4968.72,4649.53 R17.1@5063.96,4649.53
$1N3206: C4.1 Q2.1 Q3.1 R1.1 R8.2 | length 528.2
  Top Layer w8: Q2.1@4698.13,4793.86 4747.18,4744.81 4747.18,4696.86 Q3.1@4794.18,4649.86 4875.28,4649.86 R8.2@4875.61,4649.53 4875.61,4725.29 R1.1@4876.01,4725.68 4890.9,4725.68 4904.68,4739.46 4904.68,4813.25 C4.1@4849.27,4868.66
$1N3210: Q5.3 R8.1 | length 269.1
  Top Layer w8: Q5.3@4627.95,4667.26 4679.77,4615.45 R8.1@4875.61,4615.45
$1N3644: C15.2 R5.1 R13.2 R14.1 | length 288.2
  Top Layer w8: C15.2@5064.42,4762.44 5062.57,4760.58 R14.1@4968.11,4760.58 R5.1@4968.11,4841.32 4988.44,4841.32 5022.49,4875.37 R13.2@5064.42,4875.37
$1N7751: C28.1 D8.1 U3.20 | length 211.2
  Top Layer w8: U3.20@5180.85,4823.99 v1(5180.85,4877.8)
  Bottom Layer w8: C28.1@5110.98,4818.52 5129.59,4837.13 5180.85,4837.13 ; v1(5180.85,4877.8) 5180.85,4837.13 ; D8.1@5220.01,4837.13 5180.85,4837.13
$1N7797: C27.1 D7.1 U3.17 | length 172
  Top Layer w8: U3.17@5257.62,4823.99 v1(5257.62,4877.8)
  Bottom Layer w8: C27.1@5268.42,4934.96 5257.62,4924.16 v1(5257.62,4877.8) 5295.98,4839.44 D7.1@5295.98,4837.13
$1N7802: C23.1 D6.1 U3.14 | length 227.8
  Top Layer w8: U3.14@5334.4,4823.99 v1(5334.4,4877.8)
  Bottom Layer w8: v1(5334.4,4877.8) 5334.4,4874.74 D6.1@5372.01,4837.13 5463.4,4837.13 C23.1@5482.01,4818.52
$1N8638: D9.2 Q6.4 R20.2 R23.2 | length 708.8
  Top Layer w8: v1(5151.78,3786.98) Q6.4@5151.79,3827.06 ; D9.2@5591.83,3657.46 5575.33,3673.97 R20.2@5575.33,3739.49 5562.71,3752.11 R23.2@5562.71,3812.46 v1(5602.8,3812.46)
  Inner1 w8: v1(5151.78,3786.98) 5577.32,3786.98 v1(5602.8,3812.46)
$1N9075: C24.1 R24.1 | length 90.9
  Bottom Layer w8: C24.1@4225.44,3873.16 R24.1@4316.32,3873.16
$1N9358: D12.2 Q9.4 R30.2 R35.2 | length 1204.8
  Top Layer w8: v1(4947.28,3562.21) Q9.4@4947.26,3603.86 ; D12.2@5771.83,3657.46 5755.33,3673.97 R30.2@5755.33,3739.49 5742.71,3752.11 R35.2@5742.71,3812.46 v1(5782.8,3812.46)
  Inner2 w8: v1(4947.28,3562.21) 5561.23,3562.21 5782.8,3783.78 v1(5782.8,3812.46)
$1N10733: D10.2 Q7.4 R21.2 R25.2 | length 778.6
  Top Layer w8: v1(5151.78,4082.18) Q7.4@5151.79,4122.26 ; D10.2@5591.83,3952.66 5591.83,4018.19 R21.2@5575.33,4034.69 5562.71,4047.31 R25.2@5562.71,4107.66 v1(5637.68,4107.66)
  Inner1 w8: v1(5151.78,4082.18) 5612.2,4082.18 v1(5637.68,4107.66)
$1N10760: C25.1 R26.1 | length 90.9
  Bottom Layer w8: C25.1@4225.44,4010.96 R26.1@4316.32,4010.96
$1N10771: D13.2 Q10.4 R31.2 R36.2 | length 1171.2
  Top Layer w8: Q10.4@4947.26,3899.11 4973.91,3872.46 v1(5107.28,3872.46) ; D13.2@5771.83,3952.66 5755.33,3969.17 R31.2@5755.33,4034.69 5742.71,4047.31 R36.2@5742.71,4107.66 v1(5792.8,4107.66)
  Inner1 w8: v1(5107.28,3872.46) 5557.6,3872.46 v1(5792.8,4107.66)
$1N11350: D11.2 Q8.4 R22.2 R27.2 | length 618.3
  Top Layer w8: v1(5151.78,4377.48) Q8.4@5151.79,4417.56 ; v1(5515.8,4376.96) 5562.71,4376.96 ; R27.2@5562.71,4402.96 5562.71,4376.96 ; D11.2@5591.83,4247.96 5591.83,4313.49 R22.2@5575.33,4329.99 5562.71,4342.61 5562.71,4376.96
  Inner1 w8: v1(5151.78,4377.48) 5515.28,4377.48 v1(5515.8,4376.96)
$1N11377: C26.1 R28.1 | length 90.9
  Bottom Layer w8: C26.1@4225.44,4148.76 R28.1@4316.32,4148.76
$1N11388: D14.2 Q11.4 R33.2 R38.2 | length 1213.5
  Top Layer w8: Q11.4@4947.26,4194.36 4973.91,4167.71 v1@5106.93,4167.71 ; D14.2@5771.83,4247.96 5755.33,4264.47 R33.2@5755.33,4329.99 5742.71,4342.61 R38.2@5742.71,4402.96 v1(5796.4,4402.96)
  Inner1 w8: v1(5107.28,4167.71) 5621.73,4167.71 5796.4,4342.38 v1(5796.4,4402.96)
$1N20159: D22.2 Q16.4 R53.2 R58.2 | length 1312.3
  Top Layer w8: D22.2@6020.12,3952.66 6036.62,3969.17 R53.2@6036.62,4034.69 6049.24,4047.31 v1(6049.24,4075.26) R58.2@6049.24,4107.66 ; v1(6684.68,3863.64) 6959.08,3863.66 Q16.4@6994.51,3899.11 6959.07,3863.68
  Inner1 w8: v1(6303.12,3863.64) v1(6684.68,3863.64)
  Inner2 w8: v1(6049.24,4075.26) 6066.54,4057.96 6189.98,4057.96 6303.12,3944.82 v1(6303.12,3863.64)
$1N20164: D21.2 Q15.4 R52.2 R57.2 | length 1248.7
  Top Layer w8: D21.2@6020.12,4247.96 6036.62,4264.47 R52.2@6036.62,4329.99 6049.24,4342.61 v1(6049.23,4367.86) ; v1(6760.71,4158.91) 6959.07,4158.95 Q15.4@6994.51,4194.39 ; v1(6049.23,4367.86) R57.2@6049.24,4402.96 v1(6049.23,4367.86)
  Inner1 w8: v1(6049.23,4367.86) 6258.18,4158.91 v1(6564.84,4158.91)
  Inner2 w8: v1(6564.84,4158.91) v1(6760.71,4158.91)
$1N20183: C40.1 R48.1 | length 90.9
  Bottom Layer w8: R48.1@7475.64,4010.95 C40.1@7566.51,4010.95
$1N20187: D19.2 Q13.4 R43.2 R47.2 | length 481.3
  Top Layer w8: D19.2@6200.12,3952.66 6216.62,3969.17 R43.2@6216.62,4034.69 ; R43.2@6216.62,4034.69 v1(6216.58,4082.16) 6216.58,4095 R47.2@6229.24,4107.66 ; v1(6490.38,4082.17) Q13.4@6490.37,4122.26
  Inner1 w8: v1@6216.24,4082.16 v1(6490.38,4082.17)
$1N20191: C39.1 R46.1 | length 90.9
  Bottom Layer w8: R46.1@7475.64,4148.76 C39.1@7566.52,4148.76
$1N20194: D18.2 Q12.4 R42.2 R45.2 | length 468.3
  Top Layer w8: D18.2@6200.12,4247.96 6216.62,4264.47 R42.2@6216.62,4329.99 6229.24,4342.61 6229.24,4377.46 ; R45.2@6229.24,4402.96 6229.24,4377.46 ; v1(6293.85,4377.46) 6229.24,4377.46 ; v1(6490.38,4377.48) Q12.4@6490.37,4417.56
  Inner1 w8: v1(6293.85,4377.46) v1(6490.38,4377.48)
$1N20215: D23.2 Q17.4 R55.2 R60.2 | length 1329.6
  Top Layer w8: v1(6008.85,3812.46) R60.2@6048.95,3812.46 ; D23.2@6020.12,3657.46 6036.62,3673.97 R55.2@6036.62,3739.49 6049.24,3752.11 R60.2@6049.24,3812.46 ; v1(6994.48,3568.36) Q17.4@6994.51,3603.84 Q17.4@6994.71,3603.64
  Inner2 w8: v1(6008.85,3812.46) 6252.95,3568.36 v1(6994.48,3568.36)
$1N20218: C41.1 R50.1 | length 90.9
  Bottom Layer w8: R50.1@7475.64,3873.16 C41.1@7566.52,3873.16
$1N20219: D20.2 Q14.4 R44.2 R49.2 | length 547.5
  Top Layer w8: v1(6188.85,3812.46) R49.2@6229.24,3812.46 6229.24,3752.11 R44.2@6216.62,3739.49 6216.62,3673.97 D20.2@6200.12,3657.46 ; v1(6478.26,3786.98) 6478.26,3827.08
  Inner1 w8: v1(6188.85,3812.46) 6214.33,3786.98 v1(6478.26,3786.98)
$1N20229: C43.1 D17.1 U4.20 | length 212.2
  Top Layer w8: U4.20@6380.85,4823.99 v1(6380.85,4877.8)
  Bottom Layer w8: C43.1@6310.01,4818.52 6328.61,4837.13 6380.85,4837.13 ; v1(6380.85,4877.8) 6380.85,4837.13 ; D17.1@6419.98,4837.13 6380.85,4837.13
$1N20256: C42.1 D16.1 U4.17 | length 172
  Top Layer w8: U4.17@6457.62,4823.99 v1(6457.62,4877.8)
  Bottom Layer w8: C42.1@6468.42,4934.96 6468.42,4888.61 v1(6457.62,4877.8) 6495.98,4839.44 D16.1@6495.98,4837.13
$1N20257: C38.1 D15.1 U4.14 | length 226.8
  Top Layer w8: U4.14@6534.4,4823.99 v1(6534.4,4877.8)
  Bottom Layer w8: v1(6534.4,4877.8) 6571.98,4840.22 D15.1@6571.98,4837.13 6590.59,4818.52 C38.1@6680.98,4818.52
$1N36343: LED1.1 R70.1 | length 138.1
  Top Layer w20: R70.1@7424.05,5251.26 7493.41,5251.26 LED1.1@7542.01,5202.66
$1N36459: R71.1 | length 1003.8
  Top Layer w8: v1(5690.01,4993.96) R71.1@5690.01,5024.92
  Inner2 w8: v1(5690.01,4993.96) 5544.98,4993.96 5495.98,4944.96 5495.98,4714.96 5694.98,4515.96 5843.98,4515.96 v1(5869.98,4541.96)
  Bottom Layer w8: v1(5869.98,4541.96) 5896.01,4515.94 5896.01,4491.43
$1N64887: Q4.1 R16.1 R18.1 | length 200
  Top Layer w8: R16.1@7601.91,4956.64 R18.1@7601.91,4857.68 7622.27,4837.32 Q4.1@7622.27,4765.1
$1N64889: Q4.3 R7.1 | length 107.5
  Top Layer w8: Q4.3@7584.87,4686.36 7584.87,4604.82 7588.98,4600.72 7588.98,4598.89 R7.1@7601.92,4585.95
$1N69829: C14.1 Q1.1 R6.1 R7.2 | length 429.1
  Top Layer w8: C14.1@7447.79,4956.63 7437.27,4946.11 R6.1@7437.27,4857.68 7437.27,4792.35 Q1.1@7457.63,4771.99 7502.98,4726.64 7502.98,4650.8 R7.2@7567.84,4585.95
$1N79068: Q1.3 | length 158.8
  Top Layer w30: Q1.3@7420.22,4681.44 7420.22,4542.28 7434.08,4528.42
$1N124629: Q2.3 Q3.3 | length 726.8
  Top Layer w50: 4152.89,4617.96 4366.19,4831.26 Q2.3@4607.58,4831.26 4607.58,4783.32 Q3.3@4703.63,4687.27
$1N126042: D24.2 Q19.3 | length 155.5
  Bottom Layer w15: D24.2@5097.01,5220.96 5206.73,5111.24 Q19.3@5206.73,5110.96
$1N126056: Q21.1 R76.1 R77.1 | length 216.6
  Bottom Layer w8: Q21.1@5289.94,5337.59 R76.1@5405.57,5337.56 R77.1@5506.54,5337.59
$1N126057: Q21.3 R74.1 | length 210.2
  Bottom Layer w8: Q21.3@5211.2,5300.19 5364.89,5300.19 R74.1@5404.85,5260.23
$1N126058: C60.1 Q19.1 R72.1 R74.2 | length 287.1
  Bottom Layer w8: Q19.1@5297.28,5148.37 C60.1@5404.85,5148.36 ; R74.2@5404.85,5226.15 C60.1@5404.85,5148.36 ; R72.1@5506.57,5148.36 C60.1@5404.85,5148.36
$1N126455: D25.2 Q20.3 | length 123.9
  Bottom Layer w15: D25.2@4966.01,5220.96 5030.73,5156.24 Q20.3@5063.09,5156.24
